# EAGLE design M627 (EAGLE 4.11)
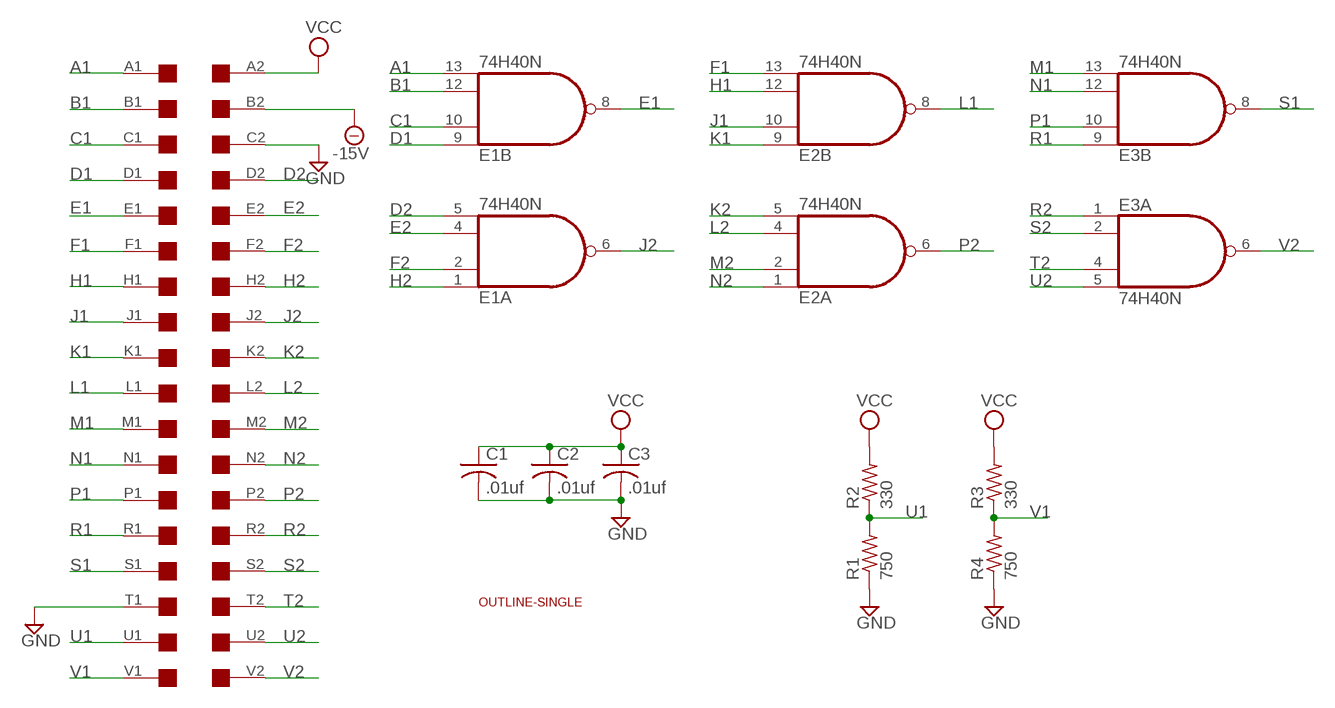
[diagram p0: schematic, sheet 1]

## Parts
C1  .01uf  C-US050-025X075  [C050-025X075]
C2  .01uf  C-US050-025X075  [C050-025X075]
C3  .01uf  C-US050-025X075  [C050-025X075]
E1  74H40N  74S20N  [DIL14]
E2  74H40N  74S20N  [DIL14]
E3  74H40N  74S20N  [DIL14]
R1  750  R-US_0207/10  [0207/10]
R2  330  R-US_0207/10  [0207/10]
R3  330  R-US_0207/10  [0207/10]
R4  750  R-US_0207/10  [0207/10]
U$1  OUTLINE-SINGLE  [SINGLE]
U$2  SINGLE  [EDGE-CON2]

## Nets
-15V: U$2.B2
A1: E1.13(B:I3) U$2.A1
B1: E1.12(B:I2) U$2.B1
C1: E1.10(B:I1) U$2.C1
D1: E1.9(B:I0) U$2.D1
D2: E1.5(A:I3) U$2.D2
E1: E1.8(B:O) U$2.E1
E2: E1.4(A:I2) U$2.E2
F1: E2.13(B:I3) U$2.F1
F2: E1.2(A:I1) U$2.F2
GND: C1.2 C2.2 C3.2 R1.1 R4.1 U$2.C2 U$2.T1
H1: E2.12(B:I2) U$2.H1
H2: E1.1(A:I0) U$2.H2
J1: E2.10(B:I1) U$2.J1
J2: E1.6(A:O) U$2.J2
K1: E2.9(B:I0) U$2.K1
K2: E2.5(A:I3) U$2.K2
L1: E2.8(B:O) U$2.L1
L2: E2.4(A:I2) U$2.L2
M1: E3.13(B:I3) U$2.M1
M2: E2.2(A:I1) U$2.M2
N1: E3.12(B:I2) U$2.N1
N2: E2.1(A:I0) U$2.N2
P1: E3.10(B:I1) U$2.P1
P2: E2.6(A:O) U$2.P2
R1: E3.9(B:I0) U$2.R1
R2: E3.1(A:I0) U$2.R2
S1: E3.8(B:O) U$2.S1
S2: E3.2(A:I1) U$2.S2
T2: E3.4(A:I2) U$2.T2
U1: R1.2 R2.1 U$2.U1
U2: E3.5(A:I3) U$2.U2
V1: R3.1 R4.2 U$2.V1
V2: E3.6(A:O) U$2.V2
VCC: C1.1 C2.1 C3.1 R2.2 R3.2 U$2.A2

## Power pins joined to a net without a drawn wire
GND: E1.7(P:GND) E2.7(P:GND) E3.7(P:GND)
VCC: E1.14(P:VCC) E2.14(P:VCC) E3.14(P:VCC)

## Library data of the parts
C1-C3 = rcl:C-US: CAPACITOR, American symbol
E1-E3 = 74xx-us:74*20: Dual 4-input NAND gate
R1-R4 = rcl:R-US_: RESISTOR, American symbol
U$1 = dec-con:OUTLINE-*: Board outlines for DEC boards.
U$2 = dec-con:SINGLE: Single-Height DEC board

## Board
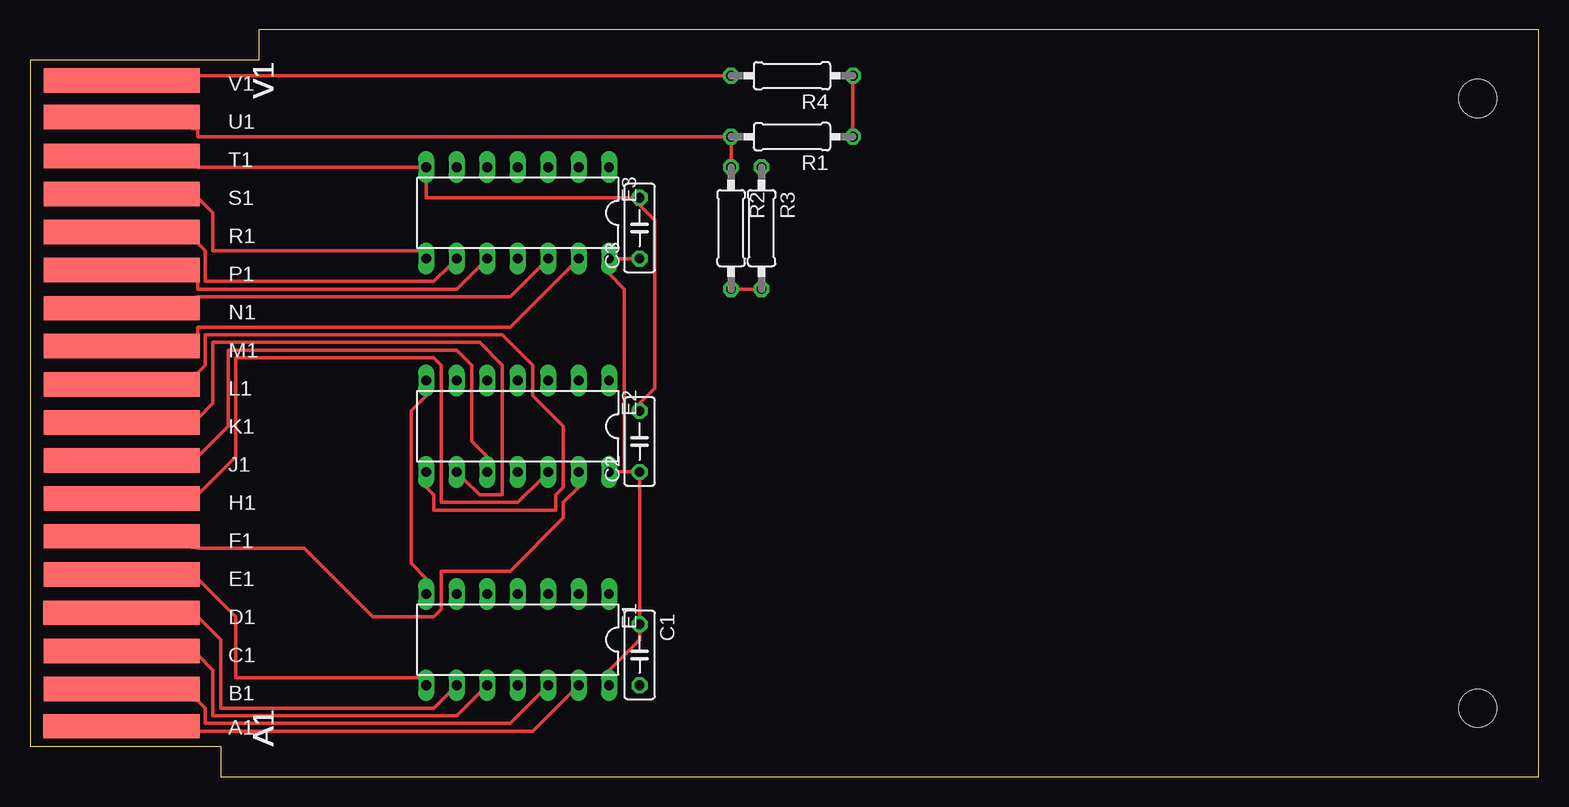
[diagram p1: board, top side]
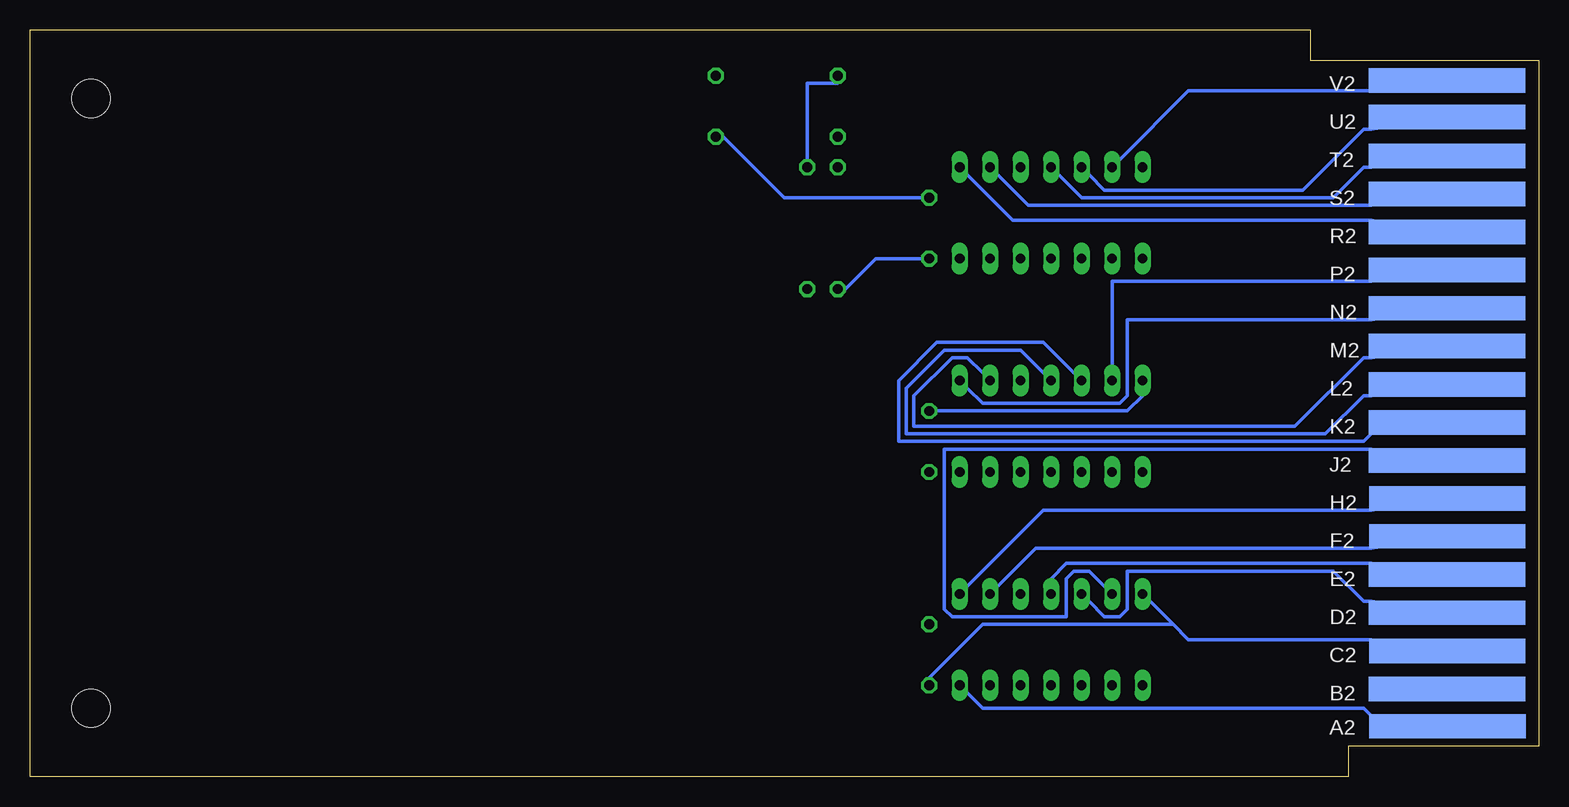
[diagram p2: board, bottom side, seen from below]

Size 125.73 x 62.23 mm. Coordinates in mm from the lower left corner, seen from the top.
Copper layers (1*16): Top 0.035mm / dielectric 1.5mm / Bottom 0.035mm
Design rules "10mils": minimum track width 12mil, minimum drill 28mil, track to track 10mil, track to pad 10mil, pad to pad 10mil, via to via 10mil, smd to smd 10mil, copper to edge 40mil, drill to drill 10mil, minimum pad ring 10mil, minimum via ring 8mil, stop-mask expansion 0mil, vias tented up to drill 0mil, thermal gap 10mil

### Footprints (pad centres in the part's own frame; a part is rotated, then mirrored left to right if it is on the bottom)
C050-025X075 = drill 0.813 octagon: 1 -2.54,0; 2 2.54,0
DIL14 = drill 0.813 long: 1 -7.62,-3.81; 2 -5.08,-3.81; 3 -2.54,-3.81; 4 0,-3.81; 5 2.54,-3.81; 6 5.08,-3.81; 7 7.62,-3.81; 8 7.62,3.81; 9 5.08,3.81; 10 2.54,3.81; 11 0,3.81; 12 -2.54,3.81; 13 -5.08,3.81; 14 -7.62,3.81
0207/10 = drill 0.813 octagon: 1 -5.08,0; 2 5.08,0
SINGLE = hole 3.175: 120.65,56.515; 120.65,5.715
EDGE-CON2 = smd 13.017 x 2.032: A1 7.633,4.207; B1 7.639,7.327; C1 7.636,10.489; D1 7.633,13.665; E1 7.642,16.84; F1 7.642,20.041; H1 7.642,23.19; J1 7.642,26.34; K1 7.642,29.515; L1 7.642,32.69; M1 7.642,35.89; N1 7.642,39.04; P1 7.642,42.24; R1 7.642,45.39; S1 7.642,48.565; T1 7.642,51.74; U1 7.642,54.966; V1 7.642,58.026 | smd 13.017 x 2.032 bottom: A2 7.614,4.207; B2 7.642,7.328; C2 7.617,10.49; D2 7.642,13.665; E2 7.642,16.84; F2 7.617,20.041; H2 7.617,23.19; J2 7.642,26.34; K2 7.642,29.515; L2 7.642,32.69; M2 7.642,35.89; N2 7.642,39.04; P2 7.642,42.24; R2 7.642,45.39; S2 7.642,48.565; T2 7.642,51.74; U2 7.642,54.966; V2 7.642,58.026

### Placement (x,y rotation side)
C1  50.8,10.16 270 top
C2  50.8,27.94 90 top
C3  50.8,45.72 90 top
E1  40.64,11.43 180 top
E2  40.64,29.21 180 top
E3  40.64,46.99 180 top
R1  63.5,53.34 180 top
R2  58.42,45.72 270 top
R3  60.96,45.72 270 top
R4  63.5,58.42 180 top
U$1  0,0 0 top
U$2  0,0 0 top

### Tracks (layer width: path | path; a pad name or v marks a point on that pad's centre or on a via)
A1
  Top 0.305: E1.13 45.09,6.99 41.91,3.81 13.97,3.81 U$2.A1
B1
  Top 0.305: E1.12 42.55,6.99 40.01,4.45 14.61,4.45 14.61,5.71 13.97,6.35 U$2.B1
C1
  Top 0.305: E1.10 37.47,6.99 35.56,5.08 15.24,5.08 15.24,8.89 13.97,10.16 U$2.C1
D1
  Top 0.305: E1.9 34.93,6.99 33.66,5.71 15.88,5.71 15.88,11.43 13.97,13.34 U$2.D1
D2
  Bottom 0.305: E1.5 37.47,14.61 36.2,13.34 34.93,13.34 34.29,13.97 34.29,17.14 17.15,17.14 14.61,14.61 13.97,14.61 U$2.D2
E1
  Top 0.305: E1.8 32.39,8.26 17.15,8.26 17.15,13.34 13.97,16.51 U$2.E1
E2
  Bottom 0.305: E1.4 40.64,16.51 39.37,17.78 13.97,17.78 U$2.E2
F1
  Top 0.305: E2.13 45.72,24.13 44.45,22.86 44.45,21.59 40.01,17.14 34.29,17.14 34.29,13.97 33.66,13.34 28.58,13.34 22.86,19.05 13.97,19.05 U$2.F1
F2
  Bottom 0.305: E1.2 45.09,15.88 41.91,19.05 13.97,19.05 U$2.F2
GND
  Top 0.305: E2.7 33.02,31.75 31.75,30.48 31.75,17.78 33.02,16.51 E1.7 | R1.1 68.58,53.98 68.58,57.78 R4.1 | U$2.T1 13.97,50.8 32.39,50.8 E3.7 33.02,49.53 33.02,48.26 50.17,48.26 C3.2 50.8,47.62 52.07,46.35 52.07,32.38 50.8,31.11 C2.2
  Bottom 0.305: E2.7 33.02,31.75 34.29,30.48 50.17,30.48 C2.2 | 30.48,12.7 29.21,11.43 13.97,11.43 U$2.C2 | 30.48,12.7 32.39,14.61 E1.7 | 30.48,12.7 46.36,12.7 50.8,8.26 C1.2 | R1.1 67.95,53.34 62.87,48.26 51.44,48.26 C3.2
H1
  Top 0.305: E2.12 42.55,24.77 40.64,22.86 34.29,22.86 34.29,34.29 33.66,34.92 17.15,34.92 17.15,26.67 13.97,23.5 U$2.H1
H2
  Bottom 0.305: E1.1 47.63,15.88 41.28,22.23 13.97,22.23 U$2.H2
J1
  Top 0.305: E2.10 38.1,26.67 36.83,27.94 36.83,34.29 35.56,35.56 16.51,35.56 16.51,29.21 13.97,26.67 U$2.J1
J2
  Bottom 0.305: E1.6 36.2,15.88 37.47,17.14 38.74,17.14 39.37,16.51 39.37,13.34 48.9,13.34 49.53,13.97 49.53,27.3 13.97,27.3 U$2.J2
K1
  Top 0.305: E2.9 36.2,24.77 37.47,23.5 39.37,23.5 39.37,34.29 37.47,36.2 15.24,36.2 15.24,31.11 13.97,29.84 U$2.K1
K2
  Bottom 0.305: E2.5 38.74,33.66 41.28,36.2 50.17,36.2 53.34,33.02 53.34,27.94 14.61,27.94 13.97,28.57 U$2.K2
L1
  Top 0.305: E2.8 33.02,24.13 33.66,23.5 33.66,22.23 43.82,22.23 43.82,23.5 44.45,24.13 44.45,29.21 41.91,31.75 41.91,34.29 39.37,36.83 14.61,36.83 14.61,34.29 13.97,33.66 U$2.L1
L2
  Bottom 0.305: E2.4 41.28,33.66 43.18,35.56 49.53,35.56 52.71,32.38 52.71,28.57 17.78,28.57 14.61,31.75 13.97,31.75 U$2.L2
M1
  Top 0.305: E3.13 45.09,42.55 40.01,37.47 13.97,37.47 13.97,36.83 U$2.M1
M2
  Bottom 0.305: E2.2 46.36,33.66 47.63,34.92 48.9,34.92 52.07,31.75 52.07,29.21 20.32,29.21 14.61,34.92 13.97,34.92 U$2.M2
N1
  Top 0.305: E3.12 42.55,42.55 40.01,40.01 13.97,40.01 U$2.N1
N2
  Bottom 0.305: E2.1 47.63,32.38 46.36,31.11 34.93,31.11 34.29,31.75 34.29,38.1 13.97,38.1 U$2.N2
P1
  Top 0.305: E3.10 37.47,42.55 35.56,40.64 13.97,40.64 13.97,41.27 U$2.P1
P2
  Bottom 0.305: E2.6 35.56,34.29 35.56,41.27 13.97,41.27 U$2.P2
R1
  Top 0.305: E3.9 34.93,42.55 33.66,41.27 14.61,41.27 14.61,43.81 13.97,44.45 U$2.R1
R2
  Bottom 0.305: E3.1 47.63,50.16 43.82,46.35 13.97,46.35 U$2.R2
S1
  Top 0.305: E3.8 32.39,43.81 15.24,43.81 15.24,46.99 13.97,48.26 U$2.S1
S2
  Bottom 0.305: E3.2 45.09,50.16 42.55,47.62 13.97,47.62 U$2.S2
T2
  Bottom 0.305: E3.4 40.01,50.16 38.1,48.26 17.15,48.26 14.61,50.8 13.97,50.8 U$2.T2
U1
  Top 0.305: R2.1 58.42,51.44 58.42,52.7 R1.2 57.79,53.34 13.97,53.34 13.97,53.98 U$2.U1
U2
  Bottom 0.305: E3.5 37.47,50.16 36.2,48.9 19.69,48.9 14.61,53.98 13.97,53.98 U$2.U2
V1
  Top 0.305: R4.2 57.79,58.42 13.97,58.42 U$2.V1
  Bottom 0.305: R3.1 60.96,51.44 60.96,57.78 58.42,57.78 R4.2
V2
  Bottom 0.305: E3.6 34.93,51.44 29.21,57.15 13.97,57.15 U$2.V2
VCC
  Top 0.305: R2.2 59.06,40.64 60.33,40.64 R3.2 | C3.1 50.17,43.18 48.9,43.18 E3.14 48.26,41.91 49.53,40.64 49.53,25.4 | 49.53,25.4 50.17,25.4 C2.1 50.8,24.77 50.8,13.34 C1.1 50.8,12.06 50.8,11.43 48.26,8.89 E1.14 | 49.53,25.4 48.9,25.4 E2.14
  Bottom 0.305: R2.2 57.79,40.64 55.25,43.18 51.44,43.18 C3.1 | U$2.A2 13.97,5.08 14.61,5.71 46.36,5.71 47.63,6.99 E1.14

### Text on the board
tNames: V1 | V1 | V1 | V1 | V1 | V1 | V1 | V1 | V1 | V1 | V1 | V1 | V1 | V1 | V1 | V1 | V1 | V1 | V1 | V1 | V1 | V1 | V1 | V1 | V1 | V1 | V1 | V1 | V1 | V1 | V1 | V1 | A1 | A1 | A1 | A1 | A1 | A1 | A1 | A1 | A1 | A1 | A1 | A1 | A1 | A1 | A1 | A1 | A1 | A1 | A1 | A1 | A1 | A1 | A1 | A1 | A1 | A1 | A1 | A1 | A1 | A1 | A1 | A1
